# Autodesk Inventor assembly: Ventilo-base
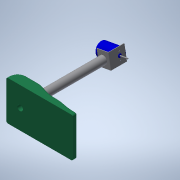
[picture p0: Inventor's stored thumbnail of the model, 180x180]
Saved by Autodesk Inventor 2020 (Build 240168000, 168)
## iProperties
Created: 2012-06
Part Number: Ventilo-base
Document SubType Name: Assembly
Designer: Bruno
Author: Bruno
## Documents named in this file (6)
- C:\Users\bruno\Documents\1-Cours-2021-22\Cours\Mécanique\Cinématique\2-Cinématique-V=W.R-Ventilo\ventilo-Inventor\Ventilo-base.iam
- C:\Users\bruno\Documents\1-Cours-2021-22\Cours\Mécanique\Cinématique\2-Cinématique-V=W.R-Ventilo\ventilo-Inventor\Axe.ipt
- C:\Users\bruno\Documents\1-Cours-2021-22\Cours\Mécanique\Cinématique\2-Cinématique-V=W.R-Ventilo\ventilo-Inventor\Axe-moteur.ipt
- C:\Users\bruno\Documents\1-Cours-2021-22\Cours\Mécanique\Cinématique\2-Cinématique-V=W.R-Ventilo\ventilo-Inventor\corps-moteur.ipt
- C:\Users\bruno\Documents\1-Cours-2021-22\Cours\Mécanique\Cinématique\2-Cinématique-V=W.R-Ventilo\ventilo-Inventor\equerre.ipt
- C:\Users\bruno\Documents\1-Cours-2021-22\Cours\Mécanique\Cinématique\2-Cinématique-V=W.R-Ventilo\ventilo-Inventor\embase-2.ipt
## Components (5 placed, 5 different names)
1. embase-2:1 — Logement:23
2. Axe:1 — Logement:12, Logement:23
3. Axe-moteur:1 — Placage:4, Affleurement:1
4. corps-moteur:1 — Placage:4, Affleurement:1, Affleurement:2, Placage:16
5. equerre:1 — Affleurement:2, Logement:12, Placage:16
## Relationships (6: Mate 2, Flush 2, Insert 2)
- Placage:4 [Mate]: Axe-moteur:1 ↔ corps-moteur:1
- Affleurement:1 [Flush]: Axe-moteur:1 ↔ corps-moteur:1
- Affleurement:2 [Flush]: corps-moteur:1 ↔ equerre:1
- Logement:12 [Insert]: Axe:1 ↔ equerre:1
- Placage:16 [Mate]: corps-moteur:1 ↔ equerre:1
- Logement:23 [Insert]: embase-2:1 ↔ Axe:1
